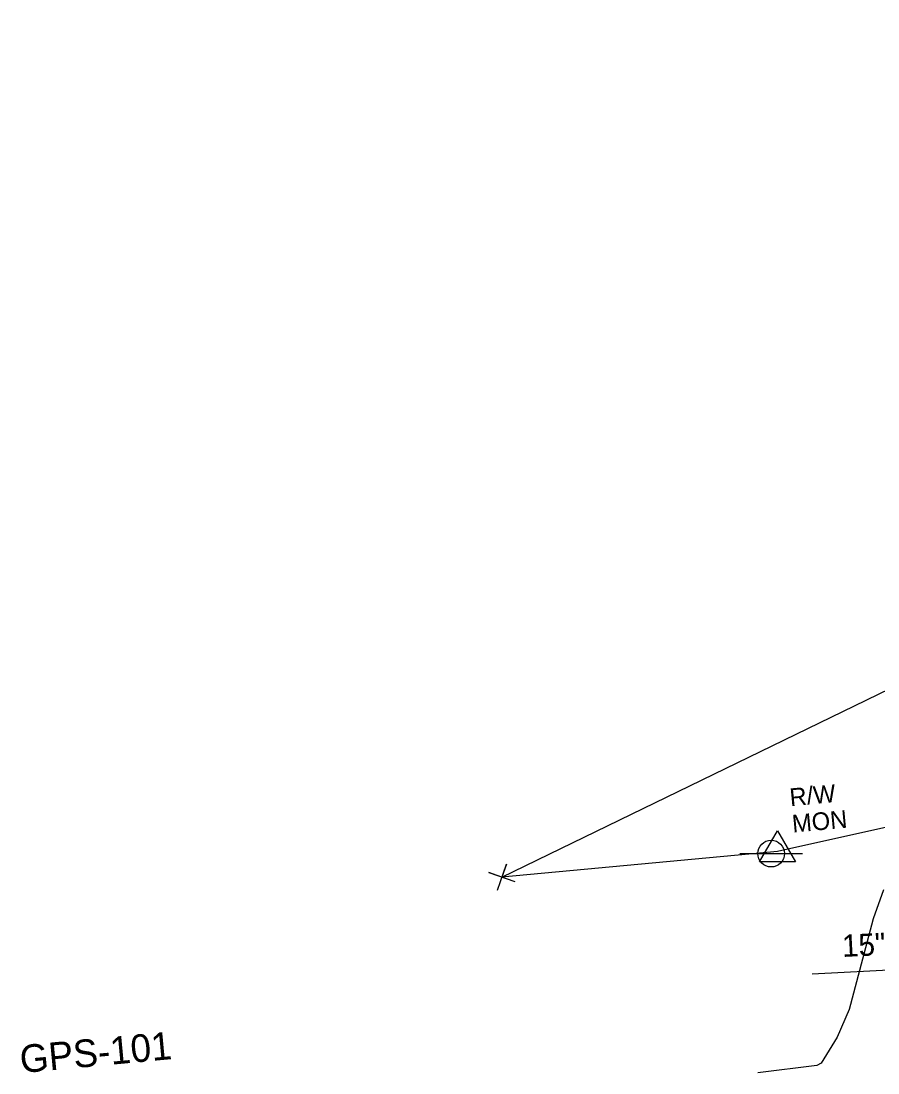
# Model space of a CAD drawing. Extents: x 553786 to 558838, y 502329 to 507342.
# Drawn here: x 553785.6 to 553940.4, y 503062.2 to 503252.3 of the extents above; entities that cross this region are included whole.
import ezdxf

# ---------------------------------------------------------------- set-up
doc = ezdxf.new("R2010")
doc.units = 0
for name, color, linetype in [('CTL Primary Horizontal and Vertical Text', 7, 'Continuous'), ('Exist Right of Way Monument Text', 7, 'Continuous'), ('Exist Structure Minor Pipes CMP 15 Inch', 7, 'Continuous'), ('Exist Structure Minor Pipes CMP 15 Inch Text', 7, 'Continuous'), ('Prop CMT DNC', 7, 'Continuous'), ('Prop Drainage Structure Pipe Alternate 36in', 7, 'Continuous'), ('Prop Drainage Structure Pipe Elbow Alternate CELL', 7, 'Continuous'), ('Prop Drainage Structure Pipe RCP 15in Class III Label', 7, 'Continuous'), ('Prop Drainage Structure Pipe RCP 48in Class III Label', 7, 'Continuous'), ('Prop Drainage Structure Plot Symbol 50 Scale', 7, 'Continuous'), ('Prop XS SE Text', 7, 'Continuous')]:
    doc.layers.add(name, color=color, linetype=linetype)

# ---------------------------------------------------------------- blocks, each defined once
blk = doc.blocks.new('EXIST RIGHT OF WAY MONUMENT')
at = {"layer": 'Prop Drainage Structure Pipe Elbow Alternate CELL'}
blk.add_line((0, 0), (0, 0), dxfattribs=at)
blk.add_lwpolyline([(-0.065, -0.0378), (0, 0.075), (0.065, -0.0378)], close=True, dxfattribs=at)

msp = doc.modelspace()

# ---------------------------------------------------------------- linework, layer by layer
at = {"layer": 'Exist Structure Minor Pipes CMP 15 Inch'}
msp.add_line((553928.49, 503080.15), (553958.8, 503081.71), dxfattribs=at)
at = {"layer": 'Prop CMT DNC'}
msp.add_line((553872.48, 503097.63), (553872.48, 503097.63), dxfattribs=at)
msp.add_lwpolyline([(553871.66, 503095.27), (553873.29, 503099.99), (553872.48, 503097.63), (553870.11, 503098.45), (553874.84, 503096.81)], dxfattribs=at)
at = {"layer": 'Prop Drainage Structure Pipe Alternate 36in'}
msp.add_lwpolyline([(553930.15, 503064.01), (553929.36, 503063.58), (553918.7, 503062.24)], dxfattribs=at)
at = {"layer": 'Prop Drainage Structure Pipe RCP 15in Class III Label'}
for p, q in [((554161.05, 503155.48), (553922.26, 503102.26)), ((553922.26, 503102.26), (553872.48, 503097.63))]:
    msp.add_line(p, q, dxfattribs=at)
at = {"layer": 'Prop Drainage Structure Pipe RCP 48in Class III Label'}
for p, q in [((553915.44, 503101.87), (553926.77, 503101.87)), ((553921.11, 503101.87), (553921.11, 503101.87))]:
    msp.add_line(p, q, dxfattribs=at)
msp.add_circle((553921.11, 503101.87), 2.41, dxfattribs=at)
at = {"layer": 'Prop Drainage Structure Plot Symbol 50 Scale'}
msp.add_lwpolyline([(553941.42, 503095.35), (553939.56, 503090.06), (553937.63, 503082.79), (553935.22, 503073.72), (553933.03, 503068.71), (553930.15, 503064.01)], dxfattribs=at)
at = {"layer": 'Prop XS SE Text'}
msp.add_line((553872.48, 503097.63), (554190.56, 503252.29), dxfattribs=at)

# ---------------------------------------------------------------- block references
at = {"layer": 'Prop Drainage Structure Pipe Elbow Alternate CELL', "xscale": 50, "yscale": 50}
msp.add_blockref('EXIST RIGHT OF WAY MONUMENT', (553922.26, 503102.26), dxfattribs=at)

# ---------------------------------------------------------------- texts
at = {"layer": 'CTL Primary Horizontal and Vertical Text'}
msp.add_text('GPS-101', height=5, rotation=5.3199, dxfattribs=at).set_placement((553785.65, 503062.21))
at = {"layer": 'Exist Right of Way Monument Text'}
for s, p in [('R/W', (553924.59, 503110.43)), ('MON', (553925.03, 503105.65))]:
    msp.add_text(s, height=3.2, rotation=5.3199, dxfattribs=at).set_placement(p)
at = {"layer": 'Exist Structure Minor Pipes CMP 15 Inch Text'}
msp.add_text('15" CMP', height=4, rotation=2.9527, dxfattribs=at).set_placement((553934.01, 503083.19))

doc.saveas('drawing.dxf')
